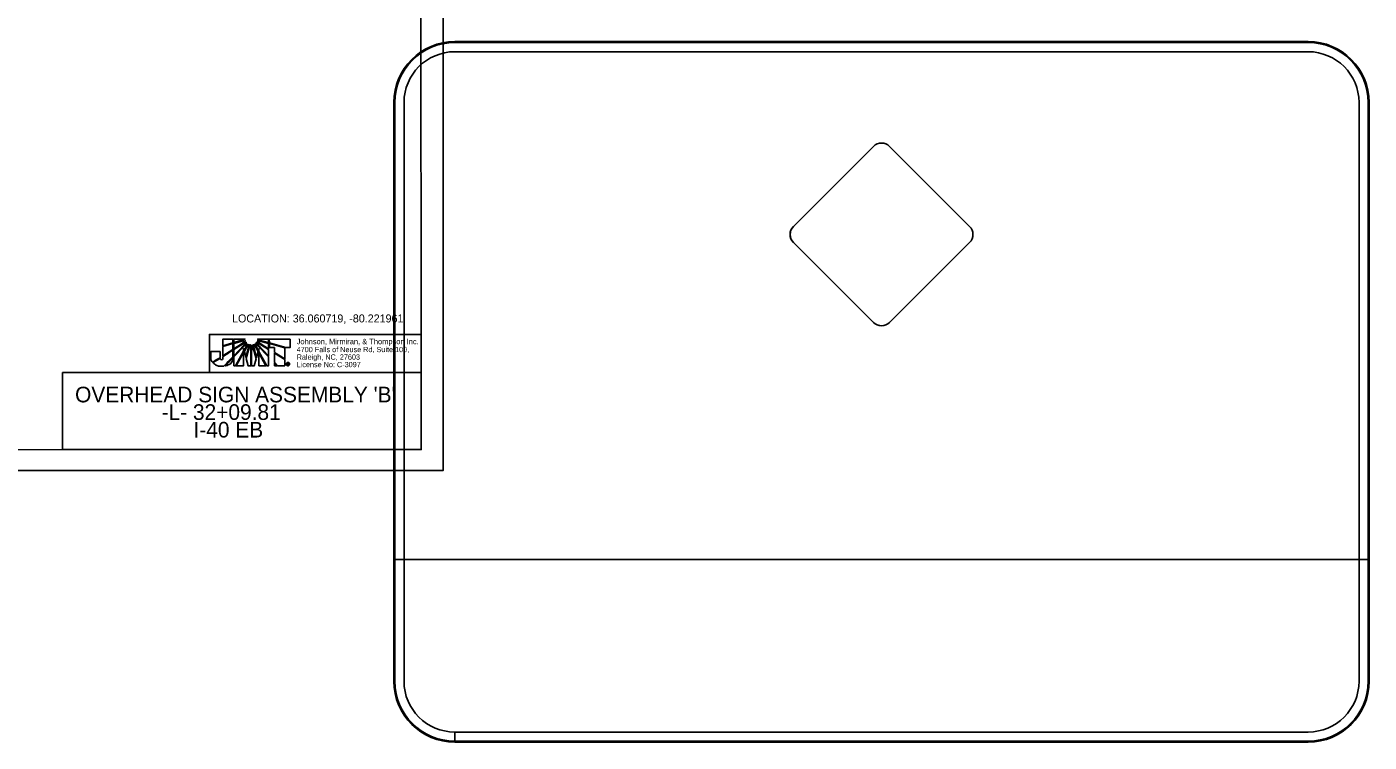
# Model space of a CAD drawing. Extents: x 1727387 to 1728895, y 539219 to 540208.
# Drawn here: x 1727645.2 to 1727898.8, y 539318.5 to 539453.8 of the extents above; entities that cross this region are included whole.
import ezdxf

# ---------------------------------------------------------------- set-up
doc = ezdxf.new("R2010")
doc.units = 0
for name, color, linetype in [('Default', 7, 'Continuous'), ('DEV BORDER CELL', 7, 'Continuous'), ('GSCOLORFILL', 7, 'Continuous'), ('GSOUTLINE', 7, 'Continuous'), ('Overhead Sheet Border', 7, 'Continuous'), ('Overhead Sheet Box', 7, 'Continuous'), ('Overhead Sheet Text', 7, 'Continuous'), ('Sheet Plot Border Outside CELL', 7, 'Continuous'), ('Sheet Sticker Exception Certification CELL', 7, 'Continuous')]:
    doc.layers.add(name, color=color, linetype=linetype)

msp = doc.modelspace()

# ---------------------------------------------------------------- linework, layer by layer
at = {"layer": 'Default'}
for p, q in [((1727684.08, 539394.7), (1727682.2, 539394.7)), ((1727682.2, 539394.7), (1727682.21, 539393.46)), ((1727682.21, 539393.46), (1727684.08, 539393.98)), ((1727684.08, 539393.85), (1727682.21, 539393.32)), ((1727682.21, 539393.32), (1727682.21, 539391.57)), ((1727684.08, 539393.98), (1727684.08, 539394.7)), ((1727684.08, 539392.76), (1727684.08, 539393.85)), ((1727686.38, 539394.72), (1727684.27, 539394.71)), ((1727684.27, 539394.71), (1727684.27, 539394.04)), ((1727684.27, 539394.04), (1727685.84, 539394.48)), ((1727685.84, 539394.33), (1727684.27, 539393.9)), ((1727684.27, 539393.9), (1727684.27, 539392.88)), ((1727684.27, 539392.88), (1727685.68, 539393.78)), ((1727685.89, 539393.75), (1727684.27, 539392.72)), ((1727684.27, 539391.55), (1727686.25, 539393.61)), ((1727686.33, 539393.51), (1727684.27, 539391.36)), ((1727685.68, 539393.78), (1727686.45, 539394.41)), ((1727685.84, 539394.48), (1727686.38, 539394.72)), ((1727686.45, 539394.41), (1727685.84, 539394.33)), ((1727686.61, 539394.12), (1727685.89, 539393.75)), ((1727686.2, 539392.58), (1727686.6, 539393.29)), ((1727686.25, 539393.61), (1727686.61, 539394.12)), ((1727686.72, 539393.25), (1727686.26, 539392.4)), ((1727686.82, 539393.89), (1727686.33, 539393.51)), ((1727686.56, 539391.28), (1727687.04, 539393.15)), ((1727686.6, 539393.29), (1727686.82, 539393.89)), ((1727687.09, 539393.72), (1727686.72, 539393.25)), ((1727687.04, 539393.15), (1727687.09, 539393.72)), ((1727687.4, 539393.64), (1727687.15, 539393.04)), ((1727687.48, 539392.16), (1727687.4, 539393.64)), ((1727687.71, 539393.64), (1727687.62, 539392.16)), ((1727687.96, 539393.04), (1727687.71, 539393.64)), ((1727688.01, 539393.73), (1727688.07, 539393.13)), ((1727688.37, 539393.25), (1727688.01, 539393.73)), ((1727688.28, 539393.89), (1727688.51, 539393.29)), ((1727688.77, 539393.51), (1727688.28, 539393.89)), ((1727688.86, 539392.37), (1727688.37, 539393.25)), ((1727688.5, 539394.12), (1727688.86, 539393.6)), ((1727689.22, 539393.76), (1727688.5, 539394.12)), ((1727688.51, 539393.29), (1727688.91, 539392.55)), ((1727688.66, 539394.41), (1727689.44, 539393.77)), ((1727689.24, 539394.34), (1727688.66, 539394.41)), ((1727690.84, 539394.71), (1727688.76, 539394.72)), ((1727688.76, 539394.72), (1727689.29, 539394.47)), ((1727690.83, 539391.34), (1727688.77, 539393.51)), ((1727688.86, 539393.6), (1727690.83, 539391.54)), ((1727690.83, 539392.74), (1727689.22, 539393.76)), ((1727690.84, 539393.89), (1727689.24, 539394.34)), ((1727689.29, 539394.47), (1727690.84, 539394.04)), ((1727689.44, 539393.77), (1727690.83, 539392.9)), ((1727690.83, 539392.9), (1727690.84, 539393.89)), ((1727690.84, 539394.04), (1727690.84, 539394.71)), ((1727694.92, 539394.72), (1727690.98, 539394.72)), ((1727690.98, 539394.72), (1727690.99, 539394)), ((1727690.99, 539394), (1727690.99, 539393.98)), ((1727690.99, 539393.98), (1727694.08, 539393.11)), ((1727690.99, 539393.86), (1727690.99, 539393.85)), ((1727693.89, 539393.04), (1727690.99, 539393.86)), ((1727690.99, 539393.85), (1727690.99, 539393.1)), ((1727694.92, 539393.11), (1727694.92, 539394.72)), ((1727682.21, 539391.57), (1727684.08, 539392.76)), ((1727684.27, 539392.72), (1727684.27, 539391.55)), ((1727684.27, 539391.36), (1727684.28, 539389.66)), ((1727684.59, 539389.66), (1727686.11, 539392.42)), ((1727686.11, 539392.15), (1727684.73, 539389.66)), ((1727686.11, 539392.42), (1727686.11, 539392.92)), ((1727686.11, 539392.92), (1727686.2, 539392.58)), ((1727686.13, 539389.66), (1727686.11, 539392.15)), ((1727686.26, 539392.4), (1727686.56, 539391.28)), ((1727687.15, 539393.04), (1727686.62, 539391.02)), ((1727686.62, 539391.02), (1727686.97, 539389.67)), ((1727687.49, 539389.67), (1727687.48, 539392.16)), ((1727687.62, 539392.16), (1727687.62, 539389.67)), ((1727688.5, 539390.99), (1727687.96, 539393.04)), ((1727688.07, 539393.13), (1727688.56, 539391.24)), ((1727688.14, 539389.67), (1727688.5, 539390.99)), ((1727688.56, 539391.24), (1727688.86, 539392.37)), ((1727688.91, 539392.55), (1727689, 539392.92)), ((1727689, 539392.92), (1727689, 539392.37)), ((1727689, 539392.37), (1727690.5, 539389.66)), ((1727690.35, 539389.67), (1727689, 539392.1)), ((1727689, 539392.1), (1727689.01, 539389.67)), ((1727690.83, 539391.54), (1727690.83, 539392.74)), ((1727690.83, 539389.66), (1727690.83, 539391.34)), ((1727690.99, 539393.1), (1727691.95, 539393.1)), ((1727691.95, 539393.1), (1727691.95, 539392.2)), ((1727691.95, 539392.2), (1727693.89, 539390.97)), ((1727691.95, 539392.05), (1727691.95, 539390.37)), ((1727693.89, 539390.83), (1727691.95, 539392.05)), ((1727693.89, 539390.97), (1727693.89, 539393.04)), ((1727693.89, 539389.67), (1727693.89, 539390.83)), ((1727694.08, 539393.11), (1727694.92, 539393.11)), ((1727684.28, 539389.66), (1727684.59, 539389.66)), ((1727684.73, 539389.66), (1727686.13, 539389.66)), ((1727686.97, 539389.67), (1727687.49, 539389.67)), ((1727687.62, 539389.67), (1727688.14, 539389.67)), ((1727689.01, 539389.67), (1727690.35, 539389.67)), ((1727690.5, 539389.66), (1727690.83, 539389.66)), ((1727691.95, 539390.37), (1727692.62, 539389.66)), ((1727692.44, 539389.66), (1727691.95, 539390.19)), ((1727691.95, 539390.19), (1727691.95, 539389.66)), ((1727691.95, 539389.66), (1727692.44, 539389.66)), ((1727692.62, 539389.66), (1727693.89, 539389.67)), ((1727694.38, 539389.84), (1727694.38, 539390.13)), ((1727694.38, 539390.13), (1727694.5, 539390.13)), ((1727694.45, 539389.84), (1727694.38, 539389.84)), ((1727694.5, 539390.07), (1727694.45, 539390.07)), ((1727694.45, 539390.07), (1727694.45, 539390.01)), ((1727694.45, 539390.01), (1727694.5, 539390.01)), ((1727694.5, 539389.95), (1727694.45, 539389.95)), ((1727694.45, 539389.95), (1727694.45, 539389.84)), ((1727694.5, 539390.3), (1727694.5, 539390.24)), ((1727694.5, 539390.24), (1727694.5, 539390.3)), ((1727694.5, 539390.13), (1727694.5, 539390.07)), ((1727694.5, 539390.07), (1727694.5, 539390.13)), ((1727694.5, 539390.13), (1727694.52, 539390.13)), ((1727694.51, 539390.07), (1727694.5, 539390.07)), ((1727694.5, 539390.01), (1727694.5, 539389.95)), ((1727694.5, 539389.95), (1727694.5, 539390.01)), ((1727694.5, 539390.01), (1727694.5, 539390.01)), ((1727694.5, 539389.95), (1727694.5, 539389.95)), ((1727694.5, 539389.73), (1727694.5, 539389.67)), ((1727694.5, 539389.67), (1727694.5, 539389.73)), ((1727694.5, 539389.73), (1727694.5, 539389.73)), ((1727694.5, 539389.67), (1727694.5, 539389.67))]:
    msp.add_line(p, q, dxfattribs=at)
msp.add_lwpolyline([(1727679.67, 539388.37), (1727719.68, 539388.37), (1727719.68, 539395.59), (1727679.67, 539395.59)], close=True, dxfattribs=at)
for points in [[(1727682.21, 539393.46), (1727684.08, 539393.98), (1727684.08, 539394.7), (1727682.2, 539394.7), (1727682.21, 539393.46)], [(1727682.21, 539391.57), (1727684.08, 539392.76), (1727684.08, 539393.85), (1727682.21, 539393.32), (1727682.21, 539391.57)], [(1727685.84, 539394.48), (1727686.38, 539394.72), (1727684.27, 539394.71), (1727684.27, 539394.04), (1727685.84, 539394.48)], [(1727684.27, 539393.9), (1727684.27, 539392.88), (1727685.68, 539393.78), (1727686.45, 539394.41), (1727685.84, 539394.33), (1727684.27, 539393.9)], [(1727684.27, 539392.72), (1727684.27, 539391.55), (1727686.25, 539393.61), (1727686.61, 539394.12), (1727685.89, 539393.75), (1727684.27, 539392.72)], [(1727686.82, 539393.89), (1727686.33, 539393.51), (1727684.27, 539391.36), (1727684.28, 539389.66), (1727684.59, 539389.66), (1727686.11, 539392.42), (1727686.11, 539392.92), (1727686.2, 539392.58), (1727686.6, 539393.29), (1727686.82, 539393.89)], [(1727687.09, 539393.72), (1727686.72, 539393.25), (1727686.26, 539392.4), (1727686.56, 539391.28), (1727687.04, 539393.15), (1727687.09, 539393.72)], [(1727687.15, 539393.04), (1727686.62, 539391.02), (1727686.97, 539389.67), (1727687.49, 539389.67), (1727687.48, 539392.16), (1727687.4, 539393.64), (1727687.15, 539393.04)], [(1727687.71, 539393.64), (1727687.62, 539392.16), (1727687.62, 539389.67), (1727688.14, 539389.67), (1727688.5, 539390.99), (1727687.96, 539393.04), (1727687.71, 539393.64)], [(1727688.01, 539393.73), (1727688.07, 539393.13), (1727688.56, 539391.24), (1727688.86, 539392.37), (1727688.37, 539393.25), (1727688.01, 539393.73)], [(1727688.28, 539393.89), (1727688.51, 539393.29), (1727688.91, 539392.55), (1727689, 539392.92), (1727689, 539392.37), (1727690.5, 539389.66), (1727690.83, 539389.66), (1727690.83, 539391.34), (1727688.77, 539393.51), (1727688.28, 539393.89)], [(1727688.5, 539394.12), (1727688.86, 539393.6), (1727690.83, 539391.54), (1727690.83, 539392.74), (1727689.22, 539393.76), (1727688.5, 539394.12)], [(1727688.66, 539394.41), (1727689.44, 539393.77), (1727690.83, 539392.9), (1727690.84, 539393.89), (1727689.24, 539394.34), (1727688.66, 539394.41)], [(1727689.29, 539394.47), (1727690.84, 539394.04), (1727690.84, 539394.71), (1727688.76, 539394.72), (1727689.29, 539394.47)], [(1727694.92, 539394.72), (1727690.98, 539394.72), (1727690.99, 539394), (1727690.99, 539393.98), (1727694.08, 539393.11), (1727694.92, 539393.11), (1727694.92, 539394.72)], [(1727690.99, 539393.86), (1727690.99, 539393.85), (1727690.99, 539393.1), (1727691.95, 539393.1), (1727691.95, 539392.2), (1727693.89, 539390.97), (1727693.89, 539393.04), (1727690.99, 539393.86)], [(1727684.73, 539389.66), (1727686.13, 539389.66), (1727686.11, 539392.15), (1727684.73, 539389.66)], [(1727689.01, 539389.67), (1727690.35, 539389.67), (1727689, 539392.1), (1727689.01, 539389.67)], [(1727691.95, 539392.05), (1727691.95, 539390.37), (1727692.62, 539389.66), (1727693.89, 539389.67), (1727693.89, 539390.83), (1727691.95, 539392.05), (1727691.95, 539392.05)], [(1727691.95, 539389.66), (1727691.95, 539389.66), (1727692.44, 539389.66), (1727691.95, 539390.19), (1727691.95, 539389.66)], [(1727694.63, 539389.91), (1727694.63, 539389.89), (1727694.63, 539389.88), (1727694.63, 539389.87), (1727694.64, 539389.84), (1727694.58, 539389.84)]]:
    msp.add_lwpolyline(points, dxfattribs=at)
for points, degree in [([(1727681.67, 539392.38), (1727681.67, 539392.38), (1727679.94, 539392.37), (1727679.94, 539392.37), (1727679.94, 539392.37), (1727679.94, 539391.29), (1727679.94, 539391.29), (1727679.94, 539391.29), (1727679.94, 539391.17), (1727679.94, 539391.17), (1727679.94, 539390.84), (1727680.05, 539390.57), (1727680.25, 539390.34), (1727680.25, 539390.34), (1727681.67, 539391.21), (1727681.67, 539391.23), (1727681.67, 539391.23), (1727681.67, 539392.38), (1727681.67, 539392.38)], 3), ([(1727681.94, 539390.82), (1727681.83, 539390.82), (1727681.73, 539390.88), (1727681.69, 539391.08), (1727681.69, 539391.08), (1727680.35, 539390.25), (1727680.35, 539390.25), (1727680.76, 539389.82), (1727681.42, 539389.56), (1727681.98, 539389.56), (1727682.13, 539389.56), (1727682.24, 539389.57), (1727682.39, 539389.6), (1727682.39, 539389.6), (1727684.08, 539391.35), (1727684.08, 539391.35), (1727684.08, 539391.35), (1727684.08, 539392.61), (1727684.08, 539392.61), (1727684.08, 539392.61), (1727682.21, 539391.42), (1727682.21, 539391.42), (1727682.21, 539390.94), (1727682.09, 539390.82), (1727681.94, 539390.82)], 3), ([(1727681.94, 539390.82), (1727681.83, 539390.82), (1727681.73, 539390.88), (1727681.69, 539391.08), (1727681.69, 539391.08), (1727680.35, 539390.25), (1727680.35, 539390.25), (1727680.76, 539389.82), (1727681.42, 539389.56), (1727681.98, 539389.56), (1727682.13, 539389.56), (1727682.24, 539389.57), (1727682.39, 539389.6), (1727682.39, 539389.6), (1727684.08, 539391.35), (1727684.08, 539391.35), (1727684.08, 539391.35), (1727684.08, 539392.61), (1727684.08, 539392.61), (1727684.08, 539392.61), (1727682.21, 539391.42), (1727682.21, 539391.42), (1727682.21, 539390.94), (1727682.09, 539390.82), (1727681.94, 539390.82)], 3), ([(1727684.08, 539391.15), (1727684.08, 539391.15), (1727682.62, 539389.64), (1727682.62, 539389.64), (1727683.34, 539389.82), (1727684.05, 539390.29), (1727684.08, 539391.15)], 3), ([(1727694.5, 539389.67), (1727694.41, 539389.67), (1727694.34, 539389.7), (1727694.28, 539389.76), (1727694.21, 539389.82), (1727694.18, 539389.9), (1727694.18, 539389.99), (1727694.18, 539390.07), (1727694.21, 539390.15), (1727694.28, 539390.21), (1727694.34, 539390.27), (1727694.41, 539390.3), (1727694.5, 539390.3)], 3), ([(1727694.5, 539390.24), (1727694.43, 539390.24), (1727694.37, 539390.21), (1727694.32, 539390.17), (1727694.27, 539390.12), (1727694.24, 539390.06), (1727694.24, 539389.99), (1727694.24, 539389.92), (1727694.27, 539389.85), (1727694.32, 539389.8), (1727694.37, 539389.75), (1727694.43, 539389.73), (1727694.5, 539389.73)], 3), ([(1727694.5, 539390.3), (1727694.59, 539390.3), (1727694.66, 539390.27), (1727694.73, 539390.21), (1727694.79, 539390.15), (1727694.82, 539390.07), (1727694.82, 539389.99)], 3), ([(1727694.5, 539389.73), (1727694.57, 539389.73), (1727694.63, 539389.75), (1727694.68, 539389.8), (1727694.73, 539389.85), (1727694.76, 539389.92), (1727694.76, 539389.99), (1727694.76, 539390.06), (1727694.73, 539390.12), (1727694.68, 539390.17), (1727694.63, 539390.21), (1727694.57, 539390.24), (1727694.5, 539390.24)], 3), ([(1727694.5, 539390.01), (1727694.54, 539390.01), (1727694.57, 539390.02), (1727694.57, 539390.04), (1727694.57, 539390.06), (1727694.55, 539390.07), (1727694.51, 539390.07)], 3), ([(1727694.82, 539389.99), (1727694.82, 539389.9), (1727694.79, 539389.82), (1727694.73, 539389.76), (1727694.67, 539389.7), (1727694.59, 539389.67), (1727694.5, 539389.67)], 3), ([(1727694.55, 539389.94), (1727694.54, 539389.95), (1727694.53, 539389.95), (1727694.5, 539389.95)], 2), ([(1727694.52, 539390.13), (1727694.59, 539390.13), (1727694.63, 539390.1), (1727694.63, 539390.04), (1727694.63, 539390.02), (1727694.62, 539390), (1727694.59, 539389.98)], 3), ([(1727694.58, 539389.84), (1727694.57, 539389.86), (1727694.56, 539389.87), (1727694.56, 539389.89), (1727694.56, 539389.92), (1727694.56, 539389.94), (1727694.55, 539389.94)], 3), ([(1727694.59, 539389.98), (1727694.61, 539389.97), (1727694.62, 539389.95), (1727694.63, 539389.91)], 2)]:
    msp.add_open_spline(points, degree=degree, dxfattribs=at)
at = {"layer": 'DEV BORDER CELL'}
msp.add_line((1727723.82, 539369.85), (1727723.82, 539369.85), dxfattribs=at)
at = {"layer": 'GSCOLORFILL'}
for p, q in [((1727887.32, 539450.97), (1727726.04, 539450.97)), ((1727887.32, 539450.97), (1727726.04, 539450.97)), ((1727887.32, 539450.97), (1727726.04, 539450.97)), ((1727726.04, 539450.78), (1727887.32, 539450.78)), ((1727726.04, 539449.05), (1727887.32, 539449.05)), ((1727714.52, 539439.45), (1727714.52, 539330.01)), ((1727714.52, 539439.45), (1727714.52, 539330.01)), ((1727714.52, 539439.45), (1727714.52, 539330.01)), ((1727714.71, 539330.01), (1727714.71, 539439.45)), ((1727716.44, 539330.01), (1727716.44, 539439.45)), ((1727896.92, 539439.45), (1727896.92, 539330.01)), ((1727898.65, 539439.45), (1727898.65, 539330.01)), ((1727898.84, 539330.01), (1727898.84, 539439.45)), ((1727898.84, 539330.01), (1727898.84, 539439.45)), ((1727898.84, 539330.01), (1727898.84, 539439.45)), ((1727898.84, 539353.06), (1727714.52, 539353.06)), ((1727714.52, 539353.06), (1727714.52, 539330.01)), ((1727714.52, 539330.01), (1727714.52, 539353.06)), ((1727714.52, 539353.06), (1727716.44, 539353.06)), ((1727714.52, 539330.01), (1727714.52, 539353.06)), ((1727714.52, 539353.06), (1727714.71, 539353.06)), ((1727714.71, 539353.06), (1727714.71, 539352.87)), ((1727714.71, 539352.87), (1727714.71, 539330.01)), ((1727716.44, 539353.06), (1727716.44, 539351.14)), ((1727896.92, 539351.14), (1727896.92, 539353.06)), ((1727896.92, 539353.06), (1727898.84, 539353.06)), ((1727898.65, 539352.87), (1727898.65, 539353.06)), ((1727898.65, 539353.06), (1727898.84, 539353.06)), ((1727898.65, 539330.01), (1727898.65, 539352.87)), ((1727898.84, 539330.01), (1727898.84, 539353.06)), ((1727898.84, 539353.06), (1727898.84, 539330.01)), ((1727898.84, 539353.06), (1727898.84, 539330.01)), ((1727716.44, 539351.14), (1727716.44, 539330.01)), ((1727896.92, 539330.01), (1727896.92, 539351.14)), ((1727726.04, 539318.49), (1727726.04, 539320.41)), ((1727726.04, 539320.41), (1727887.32, 539320.41)), ((1727887.32, 539320.41), (1727726.06, 539320.41)), ((1727726.06, 539320.41), (1727726.06, 539318.49)), ((1727726.04, 539318.49), (1727726.04, 539318.69)), ((1727887.32, 539318.69), (1727726.04, 539318.69)), ((1727726.04, 539318.69), (1727726.04, 539318.49)), ((1727726.04, 539318.69), (1727887.32, 539318.69)), ((1727726.04, 539318.49), (1727887.32, 539318.49)), ((1727726.04, 539318.49), (1727887.32, 539318.49)), ((1727726.04, 539318.49), (1727887.32, 539318.49)), ((1727887.32, 539318.49), (1727726.04, 539318.49)), ((1727887.32, 539318.49), (1727726.04, 539318.49)), ((1727726.06, 539318.49), (1727887.32, 539318.49))]:
    msp.add_line(p, q, dxfattribs=at)
for points in [[(1727790.03, 539416.02), (1727805.15, 539431.14)], [(1727790.03, 539416.02), (1727805.15, 539431.14)], [(1727805.16, 539431.14), (1727790.04, 539416.02)], [(1727808.2, 539431.14), (1727823.32, 539416.02)], [(1727808.2, 539431.14), (1727823.32, 539416.02)], [(1727823.32, 539416.02), (1727808.2, 539431.14)], [(1727805.15, 539397.85), (1727790.03, 539412.97)], [(1727805.15, 539397.85), (1727790.03, 539412.97)], [(1727790.04, 539412.98), (1727805.16, 539397.86)], [(1727808.2, 539397.86), (1727823.32, 539412.98)], [(1727823.32, 539412.97), (1727808.2, 539397.85)], [(1727823.32, 539412.97), (1727808.2, 539397.85)], [(1727806.68, 539397.23), (1727806.68, 539397.22)], [(1727806.68, 539397.22), (1727806.68, 539397.23)]]:
    msp.add_lwpolyline(points, dxfattribs=at)
for centre, radius, start, end in [((1727726.04, 539439.45), 11.52, 90, 180), ((1727726.04, 539439.45), 11.52, 90, 180), ((1727726.04, 539439.45), 11.52, 90, 180), ((1727726.04, 539439.45), 11.33, 90, 180), ((1727726.04, 539439.45), 9.6, 90, 180), ((1727887.32, 539439.45), 11.52, 0, 90), ((1727887.32, 539439.45), 11.52, 0, 90), ((1727887.32, 539439.45), 11.52, 0, 90), ((1727887.32, 539439.45), 11.33, 0, 90), ((1727887.32, 539439.45), 9.6, 0, 90), ((1727806.68, 539429.62), 2.16, 45, 135), ((1727806.68, 539429.62), 2.16, 45, 135), ((1727806.68, 539429.62), 2.15, 45, 135), ((1727791.56, 539414.5), 2.16, 135, 225), ((1727791.56, 539414.5), 2.16, 135, 225), ((1727791.56, 539414.5), 2.15, 135, 225), ((1727821.8, 539414.5), 2.16, 315, 45), ((1727821.8, 539414.5), 2.16, 315, 45), ((1727821.8, 539414.5), 2.15, 315, 45), ((1727806.68, 539399.38), 2.16, 225, 315), ((1727806.68, 539399.38), 2.16, 225, 270), ((1727806.68, 539399.38), 2.15, 225, 270), ((1727806.68, 539399.38), 2.15, 270.0151, 315), ((1727806.68, 539399.38), 2.16, 270.015, 315), ((1727726.04, 539330.01), 11.52, 180, 270), ((1727726.04, 539330.01), 11.52, 180, 270), ((1727726.04, 539330.01), 11.52, 180, 270), ((1727726.04, 539330.01), 11.52, 180, 270), ((1727726.04, 539330.01), 11.52, 180, 270), ((1727726.04, 539330.01), 11.52, 180, 270), ((1727726.04, 539330.01), 11.33, 180, 270), ((1727726.04, 539330.01), 11.33, 180, 270), ((1727726.04, 539330.01), 9.6, 180, 270), ((1727726.04, 539330.01), 9.6, 180, 270), ((1727887.32, 539330.01), 11.52, 270, 0), ((1727887.32, 539330.01), 11.52, 270, 0), ((1727887.32, 539330.01), 9.6, 270, 0), ((1727887.32, 539330.01), 11.52, 270, 0), ((1727887.32, 539330.01), 11.33, 270, 0), ((1727887.32, 539330.01), 11.52, 270, 0), ((1727887.32, 539330.01), 11.52, 270, 0), ((1727887.32, 539330.01), 9.6, 270, 0), ((1727887.32, 539330.01), 11.52, 270, 0), ((1727887.32, 539330.01), 11.33, 270, 0)]:
    msp.add_arc(centre, radius, start, end, dxfattribs=at)
at = {"layer": 'GSOUTLINE'}
for p, q in [((1727887.32, 539450.97), (1727726.04, 539450.97)), ((1727887.32, 539449.05), (1727726.04, 539449.05)), ((1727714.52, 539439.45), (1727714.52, 539330.01)), ((1727716.44, 539439.45), (1727716.44, 539330.01)), ((1727896.92, 539330.01), (1727896.92, 539439.45)), ((1727898.84, 539330.01), (1727898.84, 539439.45)), ((1727714.52, 539330.01), (1727714.52, 539353.06)), ((1727714.52, 539353.06), (1727716.44, 539353.06)), ((1727898.84, 539353.06), (1727714.52, 539353.06)), ((1727714.52, 539353.06), (1727714.52, 539330.01)), ((1727716.44, 539353.06), (1727716.44, 539351.14)), ((1727896.92, 539351.14), (1727896.92, 539353.06)), ((1727896.92, 539353.06), (1727898.84, 539353.06)), ((1727898.84, 539353.06), (1727898.84, 539330.01)), ((1727898.84, 539330.01), (1727898.84, 539353.06)), ((1727716.44, 539351.14), (1727716.44, 539330.01)), ((1727896.92, 539330.01), (1727896.92, 539351.14)), ((1727726.04, 539320.41), (1727887.32, 539320.41)), ((1727726.04, 539320.41), (1727887.32, 539320.41)), ((1727726.04, 539318.49), (1727887.32, 539318.49)), ((1727887.32, 539318.49), (1727726.04, 539318.49)), ((1727726.04, 539318.49), (1727887.32, 539318.49))]:
    msp.add_line(p, q, dxfattribs=at)
for points in [[(1727790.03, 539416.02), (1727805.15, 539431.14)], [(1727808.2, 539431.14), (1727823.32, 539416.02)], [(1727805.15, 539397.85), (1727790.03, 539412.97)], [(1727823.32, 539412.97), (1727808.2, 539397.85)]]:
    msp.add_lwpolyline(points, dxfattribs=at)
for centre, radius, start, end in [((1727726.04, 539439.45), 11.52, 90, 180), ((1727726.04, 539439.45), 9.6, 90, 180), ((1727887.32, 539439.45), 11.52, 0, 90), ((1727887.32, 539439.45), 9.6, 0, 90), ((1727806.68, 539429.62), 2.16, 45, 135), ((1727791.56, 539414.5), 2.16, 135, 225), ((1727821.8, 539414.5), 2.16, 315, 45), ((1727806.68, 539399.38), 2.16, 225, 315), ((1727726.04, 539330.01), 11.52, 180, 270), ((1727726.04, 539330.01), 11.52, 180, 270), ((1727726.04, 539330.01), 11.52, 180, 270), ((1727726.04, 539330.01), 9.6, 180, 270), ((1727726.04, 539330.01), 9.6, 180, 270), ((1727887.32, 539330.01), 11.52, 270, 0), ((1727887.32, 539330.01), 9.6, 270, 0), ((1727887.32, 539330.01), 11.52, 270, 0), ((1727887.32, 539330.01), 9.6, 270, 0), ((1727887.32, 539330.01), 11.52, 270, 0)]:
    msp.add_arc(centre, radius, start, end, dxfattribs=at)
at = {"layer": 'Overhead Sheet Border'}
msp.add_lwpolyline([(1727719.57, 539583.63), (1727419.83, 539583.47), (1727419.94, 539373.65), (1727719.68, 539373.81)], close=True, dxfattribs=at)
at = {"layer": 'Overhead Sheet Box'}
msp.add_lwpolyline([(1727651.91, 539373.81), (1727719.68, 539373.81), (1727719.68, 539388.37), (1727651.91, 539388.37)], close=True, dxfattribs=at)
at = {"layer": 'Sheet Plot Border Outside CELL'}
msp.add_lwpolyline([(1727723.82, 539589.02), (1727387.25, 539589.02), (1727387.25, 539369.85), (1727723.82, 539369.85)], close=True, dxfattribs=at)

# ---------------------------------------------------------------- texts
at = {"layer": 'Default'}
for s, height, p in [('Johnson, Mirmiran, & Thompson Inc.', 1.0222, (1727696.15, 539393.74)), ('4700 Falls of Neuse Rd, Suite 100, ', 0.993, (1727696.15, 539392.24)), ('Raleigh, NC, 27603', 0.993, (1727696.15, 539390.82)), ('License No: C-3097', 0.993, (1727696.15, 539389.4))]:
    msp.add_text(s, height=height, dxfattribs=at).set_placement(p)
at = {"layer": 'Overhead Sheet Text'}
msp.add_text('LOCATION: 36.060719, -80.221961', height=1.5128, dxfattribs=at).set_placement((1727683.94, 539397.86))
at = {"layer": 'Sheet Sticker Exception Certification CELL'}
for s, height, p in [("OVERHEAD SIGN ASSEMBLY 'B'", 2.9545, (1727654.27, 539382.75)), ('-L- 32+09.81', 2.9545, (1727670.62, 539379.43)), ('I-40 EB', 2.954, (1727676.65, 539376.1))]:
    msp.add_text(s, height=height, dxfattribs=at).set_placement(p)

doc.saveas('drawing.dxf')
